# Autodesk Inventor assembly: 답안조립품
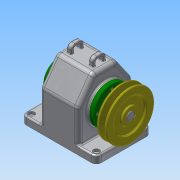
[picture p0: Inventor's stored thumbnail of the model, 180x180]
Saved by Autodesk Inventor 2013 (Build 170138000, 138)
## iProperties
Created: 2016-12
Part Number: 답안조립품
Document SubType Name: Assembly
Designer: Administrator
Author: Administrator
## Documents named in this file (15)
- C:\Users\Administrator\Desktop\461208V1010\461208V1010\답안조립품.iam
- C:\Users\Administrator\Desktop\461208V1010\본체.ipt
- C:\Users\Administrator\Desktop\461208V1010\461208V1010\앞커버.ipt
- C:\Users\Administrator\Desktop\461208V1010\461208V1010\뒤커버.ipt
- C:\Users\Administrator\Desktop\461208V1010\461208V1010\볼트 M3 x 10.ipt
- C:\Users\Administrator\Desktop\461208V1010\461208V1010\볼트 M3 x 8.ipt
- C:\Users\Administrator\Desktop\461208V1010\461208V1010\오일씰 28 40 8.ipt
- C:\Users\Administrator\Desktop\461208V1010\461208V1010\베어링 6203.ipt
- C:\Users\Administrator\Desktop\461208V1010\461208V1010\부시.ipt
- C:\Users\Administrator\Desktop\461208V1010\461208V1010\축.ipt
- C:\Users\Administrator\Desktop\461208V1010\461208V1010\키 - 6 x 6 x 22.ipt
- C:\Users\Administrator\Desktop\461208V1010\461208V1010\스퍼기어.ipt
- C:\Users\Administrator\Desktop\461208V1010\461208V1010\키 - 5 x 5 x 18.ipt
- C:\Users\Administrator\Desktop\461208V1010\461208V1010\멈춤나사 - M4x10.ipt
- C:\Users\Administrator\Desktop\461208V1010\461208V1010\V-벨트풀리.ipt
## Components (9 placed, 3 different names)
1. V-벨트풀리:1 — 각도:4
2. ISO 4762 M3 x 10:1
3. ISO 4762 M3 x 10:2
4. ISO 4762 M3 x 10:3
5. ISO 4762 M3 x 10:4
6. ISO 4762 M3 x 8:1
7. ISO 4762 M3 x 8:2
8. ISO 4762 M3 x 8:3
9. ISO 4762 M3 x 8:4
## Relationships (1: Angle 1)
- 각도:4 [Angle]: V-벨트풀리:1
